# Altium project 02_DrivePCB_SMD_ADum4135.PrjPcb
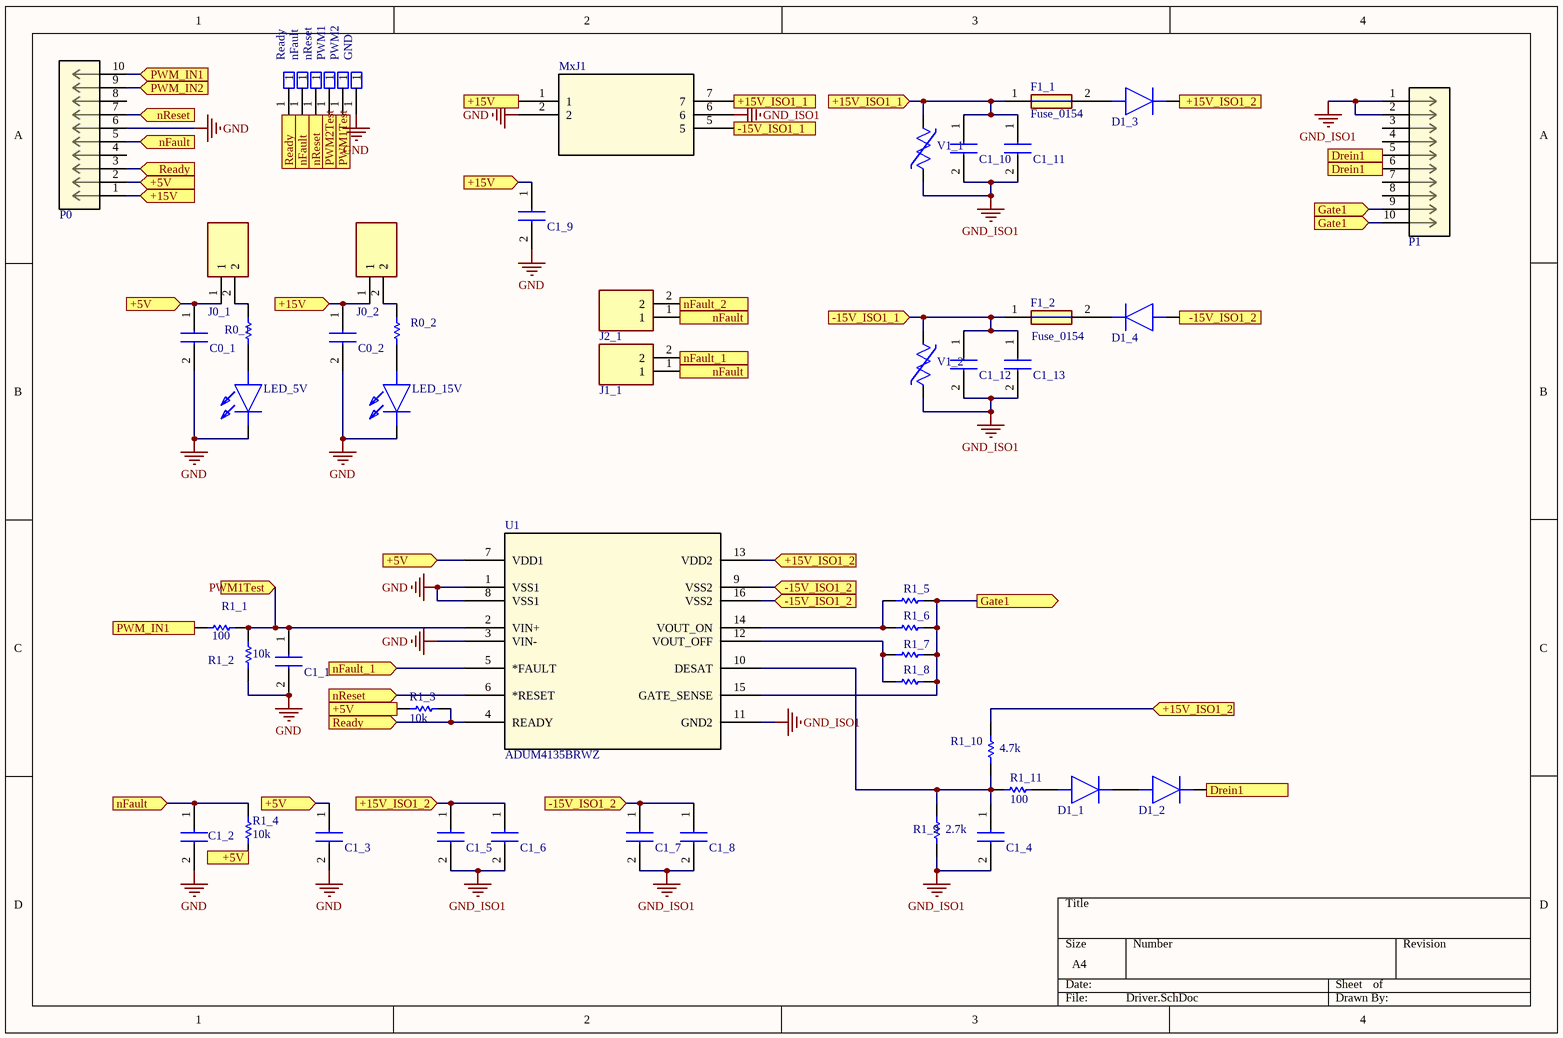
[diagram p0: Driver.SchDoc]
2 sheets, 84 parts. Net scope: flat (ports and power ports of the same name join across sheets).
Board file: Driver.PcbDoc
Sheets:
  Driver.SchDoc
  Driver2.SchDoc

## Sheet Driver.SchDoc
size A4

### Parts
C0_1  CAP  [CAP1206_SMD]  (value not drawn)
C0_2  CAP  [CAP1206_SMD]  (value not drawn)
C1_1  CAP  [CAP1206_SMD]  (value not drawn)
C1_2  CAP  [CAP1206_SMD]  (value not drawn)
C1_3  CAP  [CAP1206_SMD]  (value not drawn)
C1_4  CAP  [CAP1206_SMD]  (value not drawn)
C1_5  CAP  [CAP1206_SMD]  (value not drawn)
C1_6  CAP  [CAP_ELETRO_SMD_6.3x7.7]  (value not drawn)
C1_7  CAP  [CAP1206_SMD]  (value not drawn)
C1_8  CAP  [CAP_ELETRO_SMD_6.3x7.7]  (value not drawn)
C1_9  CAP  [CAP1206_SMD]  (value not drawn)
C1_10  CAP  [CAP1206_SMD]  (value not drawn)
C1_11  CAP  [CAP_ELETRO_SMD_6.3x7.7]  (value not drawn)
C1_12  CAP  [CAP1206_SMD]  (value not drawn)
C1_13  CAP  [CAP_ELETRO_SMD_6.3x7.7]  (value not drawn)
D1_1  TLHR5400-AS12Z  [DIODE_TH_10.1]  (value not drawn)
D1_2  TLHR5400-AS12Z  [DIODE_TH_10.1]  (value not drawn)
D1_3  TLHR5400-AS12Z  [Diode_SMD_SOD123]  (value not drawn)
D1_4  TLHR5400-AS12Z  [Diode_SMD_SOD123]  (value not drawn)
F1_1  Fuse_0154  [Fuse_0154]
F1_2  Fuse_0154  [Fuse_0154]
GND  TB004-508-02BE  [TestPoint]  (value not drawn)
J0_1  TB004-508-02BE  [HEADER_MALE_TH_2P_2.54]  (value not drawn)
J0_2  TB004-508-02BE  [HEADER_MALE_TH_2P_2.54]  (value not drawn)
J1_1  TB004-508-02BE  [HEADER_MALE_TH_2P_2.54]  (value not drawn)
J2_1  TB004-508-02BE  [HEADER_MALE_TH_2P_2.54]  (value not drawn)
LED_5V  TLHR5400-AS12Z  [LED_TH_2.54 (small)]  (value not drawn)
LED_15V  TLHR5400-AS12Z  [LED_TH_2.54 (small)]  (value not drawn)
MxJ1  MGJ2D152005SC  [MGJ2_MUR]  (value not drawn)
nFault  TB004-508-02BE  [TestPoint]  (value not drawn)
nReset  TB004-508-02BE  [TestPoint]  (value not drawn)
P0  5103311-1  [CONN_5103311-1_TYC]  (value not drawn)
P1  5103311-1  [CONN_5103311-1_TYC]  (value not drawn)
PWM1  TB004-508-02BE  [TestPoint]  (value not drawn)
PWM2  TB004-508-02BE  [TestPoint]  (value not drawn)
R0_1  (no value)  [Resis_SMD_1206]
R0_2  (no value)  [Resis_SMD_1206]
R1_1  Name: 100  [Resis_SMD_1206]
R1_2  Name: 10k  [Resis_SMD_1206]
R1_3  Name: 10k  [Resis_SMD_1206]
R1_4  Name: 10k  [Resis_SMD_1206]
R1_5  Res1  [Resis_SMD_1206]  (value not drawn)
R1_6  Res1  [Resis_SMD_1206]  (value not drawn)
R1_7  Res1  [Resis_SMD_1206]  (value not drawn)
R1_8  Res1  [Resis_SMD_1206]  (value not drawn)
R1_9  Name: 2.7k  [Resis_SMD_1206]
R1_10  Name: 4.7k  [Resis_SMD_1206]
R1_11  Name: 100  [Resis_SMD_1206]
Ready  TB004-508-02BE  [TestPoint]  (value not drawn)
U1  ADUM4135BRWZ  [RW_16_ADI-M]
V1_1  B72220S131K101  [Varist]  (value not drawn)
V1_2  B72220S131K101  [Varist]  (value not drawn)

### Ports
+5V (in), +15V (in), +15V_ISO1_1 (in), +15V_ISO1_2 (in), -15V_ISO1_1 (in), -15V_ISO1_2 (in), Drein1 (in), Drein1 (out), Gate1 (in), Gate1 (out), nFault (in), nFault_1 (in), nFault_2 (in), nReset (in), PWM1Test (in), PWM2Test (in), PWM_IN1 (in), PWM_IN2 (in), Ready (in)

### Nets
GND: C0_1.2 C0_2.2 C1_1.2 C1_2.2 C1_3.2 C1_9.2 GND.1 LED_5V.1(K) LED_15V.1(K) MxJ1.2 P0.6 R1_2.1 U1.1(VSS1) U1.3(VIN-) U1.8(VSS1)
GND_ISO1: C1_4.2 C1_5.2 C1_6.2 C1_7.2 C1_8.2 C1_10.2 C1_11.2 C1_12.2 C1_13.2 MxJ1.6 P1.1 P1.2 R1_9.1 U1.11(GND2) V1_1.2 V1_2.2
NetC0_1_1: C0_1.1 C1_3.1 J0_1.1 P0.2 R1_3.2 R1_4.2 U1.7(VDD1) ; port +5V
NetC0_2_1: C0_2.1 C1_9.1 J0_2.1 MxJ1.1 P0.1 ; port +15V
NetC1_1_1: C1_1.1 PWM2.1 R1_1.2 R1_2.2 U1.2(VIN+) ; port PWM1Test
NetC1_2_1: C1_2.1 J1_1.1 J2_1.1 nFault.1 P0.5 R1_4.1 ; port nFault
NetC1_4_1: C1_4.1 R1_9.2 R1_10.1 R1_11.1 U1.10(DESAT)
NetC1_5_1: C1_5.1 C1_6.1 D1_3.1(K) R1_10.2 U1.13(VDD2) ; port +15V_ISO1_2
NetC1_7_1: C1_7.1 C1_8.1 D1_4.2(A) U1.9(VSS2) U1.16(VSS2) ; port -15V_ISO1_2
NetC1_10_1: C1_10.1 C1_11.1 F1_1.1 MxJ1.7 V1_1.1 ; port +15V_ISO1_1
NetC1_12_1: C1_12.1 C1_13.1 F1_2.1 MxJ1.5 V1_2.1 ; port -15V_ISO1_1
NetC2_1_1: PWM1.1 ; port PWM2Test
NetD1_1_1: D1_1.1(K) D1_2.2(A)
NetD1_1_2: D1_1.2(A) R1_11.2
NetD1_2_1: D1_2.1(K) P1.5 P1.6 ; port Drein1
NetD1_3_2: D1_3.2(A) F1_1.2
NetD1_4_1: D1_4.1(K) F1_2.2
NetJ0_1_2: J0_1.2 R0_1.2
NetJ0_2_2: J0_2.2 R0_2.2
NetJ1_1_2: J1_1.2 U1.5(*FAULT) ; port nFault_1
NetJ2_1_2: J2_1.2 ; port nFault_2
NetLED_5V_2: LED_5V.2(A) R0_1.1
NetLED_15V_2: LED_15V.2(A) R0_2.1
NetnReset_1: nReset.1 P0.7 U1.6(*RESET) ; port nReset
NetP0_3: P0.3 R1_3.1 Ready.1 U1.4(READY) ; port Ready
NetP0_9: P0.9 ; port PWM_IN2
NetP0_10: P0.10 R1_1.1 ; port PWM_IN1
NetP1_9: P1.9 P1.10 R1_5.2 R1_6.2 R1_7.2 R1_8.2 U1.15(GATE_SENSE) ; port Gate1
NetR1_5_1: R1_5.1 R1_6.1 U1.14(VOUT_ON)
NetR1_7_1: R1_7.1 R1_8.1 U1.12(VOUT_OFF)

Not connected (* = marked no-connect by the designer): P0 4 8; P1 3 4 7 8

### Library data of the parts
C0_1 C0_2 C1_1-C1_13 = CAP: Capacitor; Manufacturer_Name: Kemet; Manufacturer_Part_Number: C1206X475K3RACAUTO7210
D1_1-D1_4 = Diode: Manufacturer_Name: Vishay
F1_1 F1_2 = Fuse_0154: Fuse; Manufacturer_Name: LITTELFUSE; Manufacturer_Part_Number: 0154002.DRL
GND nFault nReset PWM1 PWM2 Ready = TestPoint: Connector; Manufacturer_Name: CUI Devices
J0_1 J0_2 J1_1 J2_1 = Con_Header_2P: Connector; Manufacturer_Name: CUI Devices
LED_5V LED_15V = LED: Manufacturer_Name: Vishay
MxJ1 = MGJ2D152005SC: No Description Available; Mfr_Name: Murata
P0 P1 = Con_Header_5103311-1: No Description Available; Mfr_Name: TE Connectivity
R0_1 R0_2 = Resistor: Name: 2.7k
R1_1-R1_11 = Resistor
U1 = ADUM4135BRWZ: No Description Available; Mfr_Name: Analog Devices Inc
V1_1 V1_2 = Varistor: No Description Available; Mfr_Name: TDK

## Sheet Driver2.SchDoc
size A4
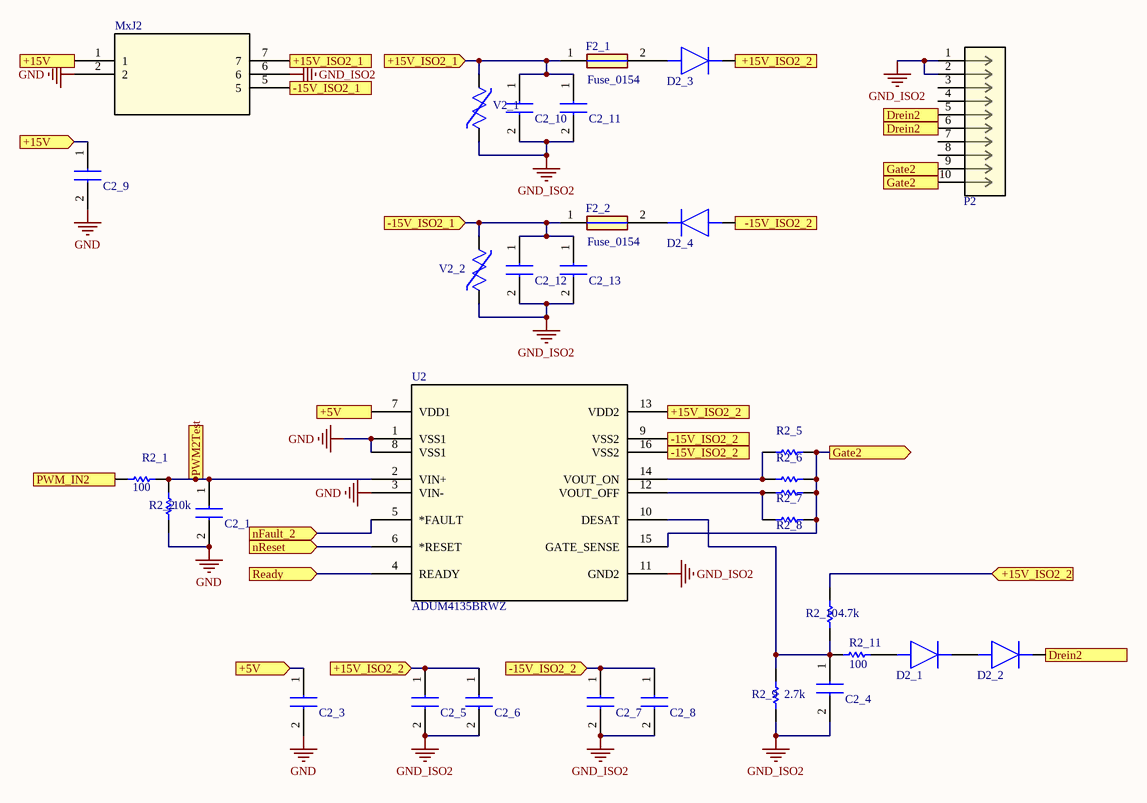
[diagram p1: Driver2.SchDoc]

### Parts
C2_1  CAP  [CAP1206_SMD]  (value not drawn)
C2_3  CAP  [CAP1206_SMD]  (value not drawn)
C2_4  CAP  [CAP1206_SMD]  (value not drawn)
C2_5  CAP  [CAP1206_SMD]  (value not drawn)
C2_6  CAP  [CAP_ELETRO_SMD_6.3x7.7]  (value not drawn)
C2_7  CAP  [CAP1206_SMD]  (value not drawn)
C2_8  CAP  [CAP_ELETRO_SMD_6.3x7.7]  (value not drawn)
C2_9  CAP  [CAP1206_SMD]  (value not drawn)
C2_10  CAP  [CAP1206_SMD]  (value not drawn)
C2_11  CAP  [CAP_ELETRO_SMD_6.3x7.7]  (value not drawn)
C2_12  CAP  [CAP1206_SMD]  (value not drawn)
C2_13  CAP  [CAP_ELETRO_SMD_6.3x7.7]  (value not drawn)
D2_1  TLHR5400-AS12Z  [DIODE_TH_10.1]  (value not drawn)
D2_2  TLHR5400-AS12Z  [DIODE_TH_10.1]  (value not drawn)
D2_3  TLHR5400-AS12Z  [Diode_SMD_SOD123]  (value not drawn)
D2_4  TLHR5400-AS12Z  [Diode_SMD_SOD123]  (value not drawn)
F2_1  Fuse_0154  [Fuse_0154]
F2_2  Fuse_0154  [Fuse_0154]
MxJ2  MGJ2D152005SC  [MGJ2_MUR]  (value not drawn)
P2  5103311-1  [CONN_5103311-1_TYC]  (value not drawn)
R2_1  Name: 100  [Resis_SMD_1206]
R2_2  Name: 10k  [Resis_SMD_1206]
R2_5  Res1  [Resis_SMD_1206]  (value not drawn)
R2_6  Res1  [Resis_SMD_1206]  (value not drawn)
R2_7  Res1  [Resis_SMD_1206]  (value not drawn)
R2_8  Res1  [Resis_SMD_1206]  (value not drawn)
R2_9  Name: 2.7k  [Resis_SMD_1206]
R2_10  Name: 4.7k  [Resis_SMD_1206]
R2_11  Name: 100  [Resis_SMD_1206]
U2  ADUM4135BRWZ  [RW_16_ADI-M]
V2_1  B72220S131K101  [Varist]  (value not drawn)
V2_2  B72220S131K101  [Varist]  (value not drawn)

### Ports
+5V (in), +15V (in), +15V_ISO2_1 (in), +15V_ISO2_2 (in), -15V_ISO2_1 (in), -15V_ISO2_2 (in), Drein2 (in), Drein2 (out), Gate2 (in), Gate2 (out), nFault_2 (in), nReset (in), PWM2Test (in), PWM_IN2 (in), Ready (in)

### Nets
GND: C2_1.2 C2_3.2 C2_9.2 MxJ2.2 R2_2.1 U2.1(VSS1) U2.3(VIN-) U2.8(VSS1)
GND_ISO2: C2_4.2 C2_5.2 C2_6.2 C2_7.2 C2_8.2 C2_10.2 C2_11.2 C2_12.2 C2_13.2 MxJ2.6 P2.1 P2.2 R2_9.1 U2.11(GND2) V2_1.2 V2_2.2
NetC0_1_1: C2_3.1 U2.7(VDD1) ; port +5V
NetC0_2_1: C2_9.1 MxJ2.1 ; port +15V
NetC2_1_1: C2_1.1 R2_1.2 R2_2.2 U2.2(VIN+) ; port PWM2Test
NetC2_4_1: C2_4.1 R2_9.2 R2_10.1 R2_11.1 U2.10(DESAT)
NetC2_5_1: C2_5.1 C2_6.1 D2_3.1(K) R2_10.2 U2.13(VDD2) ; port +15V_ISO2_2
NetC2_7_1: C2_7.1 C2_8.1 D2_4.2(A) U2.9(VSS2) U2.16(VSS2) ; port -15V_ISO2_2
NetC2_10_1: C2_10.1 C2_11.1 F2_1.1 MxJ2.7 V2_1.1 ; port +15V_ISO2_1
NetC2_12_1: C2_12.1 C2_13.1 F2_2.1 MxJ2.5 V2_2.1 ; port -15V_ISO2_1
NetD2_1_1: D2_1.1(K) D2_2.2(A)
NetD2_1_2: D2_1.2(A) R2_11.2
NetD2_2_1: D2_2.1(K) P2.5 P2.6 ; port Drein2
NetD2_3_2: D2_3.2(A) F2_1.2
NetD2_4_1: D2_4.1(K) F2_2.2
NetJ2_1_2: U2.5(*FAULT) ; port nFault_2
NetnReset_1: U2.6(*RESET) ; port nReset
NetP0_3: U2.4(READY) ; port Ready
NetP0_9: R2_1.1 ; port PWM_IN2
NetP2_9: P2.9 P2.10 R2_5.2 R2_6.2 R2_7.2 R2_8.2 U2.15(GATE_SENSE) ; port Gate2
NetR2_5_1: R2_5.1 R2_6.1 U2.14(VOUT_ON)
NetR2_7_1: R2_7.1 R2_8.1 U2.12(VOUT_OFF)

Not connected (* = marked no-connect by the designer): P2 3 4 7 8

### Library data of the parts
C2_1 C2_3-C2_13 = CAP: as C0_1 on sheet Driver
D2_1-D2_4 = Diode: Manufacturer_Name: Vishay
F2_1 F2_2 = Fuse_0154: as F1_1 on sheet Driver
MxJ2 = MGJ2D152005SC: as MxJ1 on sheet Driver
P2 = Con_Header_5103311-1: as P0 on sheet Driver
R2_1 R2_2 R2_5-R2_11 = Resistor
U2 = ADUM4135BRWZ: as U1 on sheet Driver
V2_1 V2_2 = Varistor: No Description Available; Mfr_Name: TDK

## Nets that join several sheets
GND: Driver (15 pins), Driver2 (8 pins)
NetC0_1_1: Driver (7 pins), Driver2 (C2_3.1 U2.7)
NetC0_2_1: Driver (5 pins), Driver2 (C2_9.1 MxJ2.1)
NetC2_1_1: Driver (PWM1.1), Driver2 (C2_1.1 R2_1.2 R2_2.2 U2.2)
NetJ2_1_2: Driver (J2_1.2), Driver2 (U2.5)
NetnReset_1: Driver (nReset.1 P0.7 U1.6), Driver2 (U2.6)
NetP0_3: Driver (P0.3 R1_3.1 Ready.1 U1.4), Driver2 (U2.4)
NetP0_9: Driver (P0.9), Driver2 (R2_1.1)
